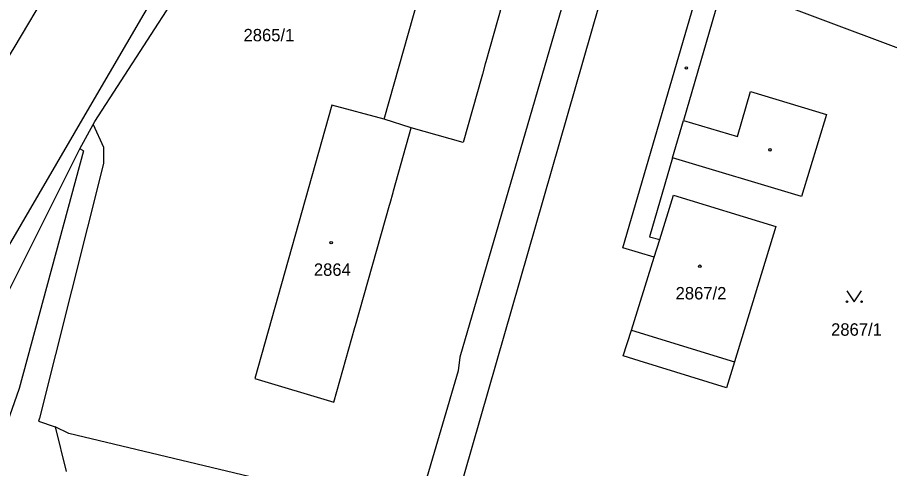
# Model space of a CAD drawing. Extents: x -527335 to -526256, y -1079142 to -1077836.
# Drawn here: x -527116.6 to -526997.2, y -1078938.8 to -1078877.1 of the extents above; entities that cross this region are included whole.
import ezdxf

# ---------------------------------------------------------------- set-up
doc = ezdxf.new("R2010")
doc.units = 0
for name, color, linetype in [('Hranice parcel', 7, 'Continuous'), ('Parcelní čísla', 7, 'Continuous'), ('Vnitřní kresba', 7, 'Continuous'), ('Značky budov', 7, 'Continuous'), ('Značky kultur', 7, 'Continuous')]:
    doc.layers.add(name, color=color, linetype=linetype)

msp = doc.modelspace()

# ---------------------------------------------------------------- linework, layer by layer
at = {"layer": 'Hranice parcel'}
for p, q in [((-527062.72, -1078892.18), (-527066.43, -1078890.98)), ((-527111.47, -1078933.13), (-527109.99, -1078939.25))]:
    msp.add_line(p, q, dxfattribs=at)
for points in [[(-526998.63, -1078724.92), (-527007.36, -1078735.07), (-527019.76, -1078750.86), (-527025.21, -1078757.99), (-527037.26, -1078775.41), (-527043.97, -1078785.5), (-527052.05, -1078797.8), (-527057.33, -1078806.06), (-527064.89, -1078818.36), (-527077.97, -1078839.97), (-527106.45, -1078888.73), (-527179.38, -1079013.92), (-527179.74, -1079015.3)], [(-527106.29, -1078891.74), (-527106.04, -1078891.29), (-527091.65, -1078868.97), (-527075.33, -1078840.18), (-527060.55, -1078815.59)], [(-527066.43, -1078890.98), (-527061.74, -1078874.35), (-527053.44, -1078844.9), (-527050.62, -1078834.87), (-527039.79, -1078837.98), (-527052.51, -1078883.15), (-527052.59, -1078883.43), (-527052.98, -1078884.85), (-527053.07, -1078885.16), (-527055.62, -1078894.2), (-527062.72, -1078892.18)], [(-527036.12, -1078871.48), (-527040.52, -1078870.12), (-527056.07, -1078923.59), (-527056.32, -1078925.44), (-527061.28, -1078942.36), (-527061.88, -1078943.73), (-527062.74, -1078944.48), (-527063.56, -1078944.86), (-527064.35, -1078944.84), (-527109.61, -1078934.05), (-527111.47, -1078933.13)], [(-526995.85, -1078962.29), (-527010.74, -1078958.5), (-527025.58, -1078954.47), (-527044.12, -1078949.38), (-527051.99, -1078948.07), (-527054.24, -1078947.27), (-527055.63, -1078946.46), (-527056.51, -1078945.37), (-527056.83, -1078944.49), (-527056.47, -1078943.22), (-527035.9, -1078871.55), (-527036.12, -1078871.48)], [(-527019.98, -1078872.28), (-527025.47, -1078891.17), (-527018.06, -1078893.37), (-527016.26, -1078887.19), (-527005.85, -1078890.36), (-527009.3, -1078901.58), (-527026.96, -1078896.29), (-527030.11, -1078907.12), (-527028.71, -1078907.46), (-527026.81, -1078901.4), (-527012.81, -1078905.7), (-527018.48, -1078924.2), (-527019.58, -1078927.78), (-527031.54, -1078924.07), (-527033.7, -1078923.4), (-527032.59, -1078919.86), (-527029.47, -1078909.9), (-527033.77, -1078908.6), (-527022.83, -1078871.21)], [(-527131.27, -1078905.61), (-527124.93, -1078894.36), (-527124.67, -1078892.26), (-527123.81, -1078892.07), (-527117.09, -1078881.21), (-527112.22, -1078872.94)], [(-526976.78, -1078885.88), (-526979.42, -1078886.96), (-526982.31, -1078886.42), (-527019.98, -1078872.28)], [(-527066.43, -1078890.98), (-527073.61, -1078889.05), (-527084.15, -1078926.5), (-527073.32, -1078929.74), (-527070.43, -1078919.51), (-527070.35, -1078919.22), (-527065.7, -1078902.75), (-527065.63, -1078902.48), (-527065.22, -1078901.04), (-527065.15, -1078900.79), (-527062.72, -1078892.18)], [(-527126.23, -1078935.36), (-527125.35, -1078933.57), (-527121.28, -1078926.64), (-527120.64, -1078924.51), (-527120.09, -1078923.34), (-527121.81, -1078922.35), (-527108.1, -1078895.05), (-527106.29, -1078891.74)], [(-527106.29, -1078891.74), (-527104.88, -1078894.82), (-527104.88, -1078897.08), (-527113.64, -1078931.93), (-527113.75, -1078932.35), (-527111.47, -1078933.13)]]:
    msp.add_lwpolyline(points, dxfattribs=at)
at = {"layer": 'Vnitřní kresba'}
for p, q in [((-527026.96, -1078896.29), (-527025.47, -1078891.17)), ((-527107.6, -1078895.32), (-527116.41, -1078927.85)), ((-527107.6, -1078895.32), (-527108.1, -1078895.05)), ((-527029.47, -1078909.9), (-527028.71, -1078907.46)), ((-527032.59, -1078919.86), (-527018.48, -1078924.2)), ((-527116.41, -1078927.85), (-527120.12, -1078938.41))]:
    msp.add_line(p, q, dxfattribs=at)
at = {"layer": 'Značky budov'}
for centre in [(-527025.06, -1078883.98), (-527013.61, -1078895.18), (-527073.7, -1078907.9), (-527023.22, -1078911.13)]:
    msp.add_circle(centre, 0.175, dxfattribs=at)
at = {"layer": 'Značky kultur'}
msp.add_lwpolyline([(-527003.07, -1078914.48), (-527002.07, -1078915.98), (-527001.07, -1078914.48)], dxfattribs=at)
for centre in [(-527003.07, -1078915.98), (-527001.07, -1078915.98)]:
    msp.add_circle(centre, 0.1, dxfattribs=at)

# ---------------------------------------------------------------- texts
at = {"layer": 'Parcelní čísla'}
for s, p in [('2865/1', (-527085.69, -1078880.33)), ('2864', (-527076.06, -1078912.44)), ('2867/2', (-527026.53, -1078915.67)), ('2867/1', (-527005.24, -1078920.64))]:
    msp.add_text(s, height=1.7, dxfattribs=at).set_placement(p)

doc.saveas('drawing.dxf')
